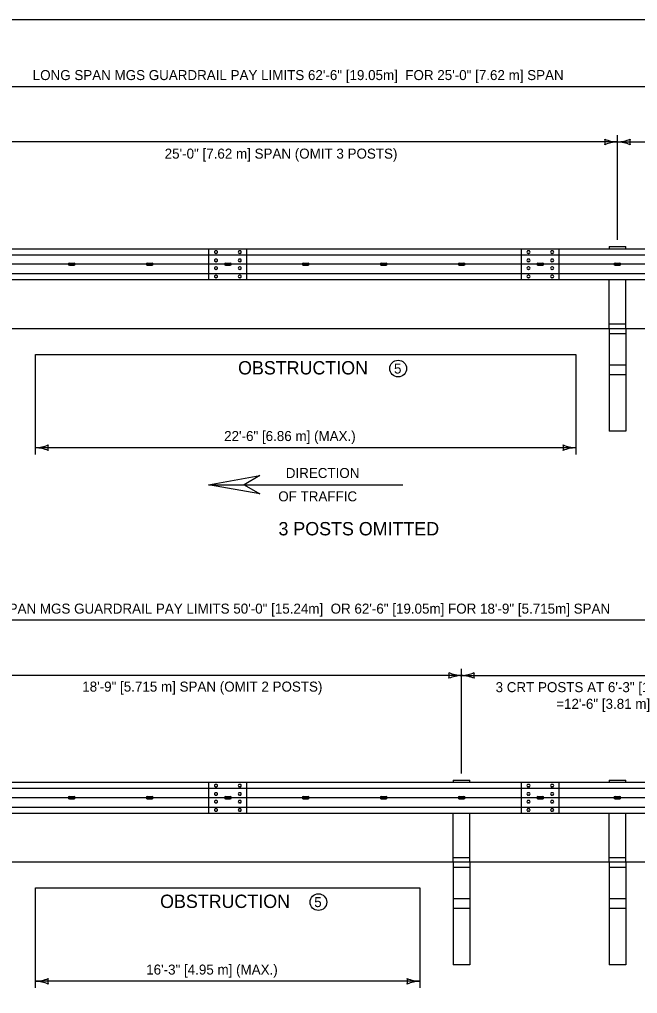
# Model space of a CAD drawing. Extents: x 49991.4 to 50021, y 49987.6 to 50011.4.
# Drawn here: x 50003.46 to 50007.16, y 49993.16 to 49999 of the extents above; entities that cross this region are included whole.
import ezdxf

# ---------------------------------------------------------------- set-up
doc = ezdxf.new("R2010")
doc.units = 0
for name, color, linetype in [('Level 1', 7, 'Continuous'), ('Level 2', 7, 'Continuous'), ('Level 3', 7, 'Continuous'), ('Level 4', 7, 'Continuous'), ('Level 5', 7, 'Continuous')]:
    doc.layers.add(name, color=color, linetype=linetype)

msp = doc.modelspace()

# ---------------------------------------------------------------- linework, layer by layer
at = {"layer": 'Level 1'}
for p, q in [((50000.0289, 49997.6246), (50011.2949, 49997.6246)), ((50004.5961, 49997.4394), (50004.5961, 49997.6239)), ((50004.6403, 49997.6123), (50004.6367, 49997.6123)), ((50004.6403, 49997.5973), (50004.6367, 49997.5973)), ((50004.7825, 49997.6123), (50004.7789, 49997.6123)), ((50004.7825, 49997.5973), (50004.7789, 49997.5973)), ((50006.4686, 49997.4394), (50006.4686, 49997.6239)), ((50006.5128, 49997.6123), (50006.5092, 49997.6123)), ((50006.5128, 49997.5973), (50006.5092, 49997.5973)), ((50006.655, 49997.6123), (50006.6514, 49997.6123)), ((50006.655, 49997.5973), (50006.6514, 49997.5973)), ((50006.9944, 49997.6379), (50006.9944, 49997.6246)), ((50006.9944, 49997.6379), (50007.0944, 49997.6379)), ((50007.0944, 49997.6246), (50007.0944, 49997.6379)), ((50000.0289, 49997.5886), (50011.2949, 49997.5886)), ((50003.7593, 49997.5386), (50003.7884, 49997.5386)), ((50004.2265, 49997.5386), (50004.2557, 49997.5386)), ((50004.6403, 49997.5624), (50004.6367, 49997.5624)), ((50004.6403, 49997.5474), (50004.6367, 49997.5474)), ((50004.6947, 49997.5386), (50004.7239, 49997.5386)), ((50004.7825, 49997.5624), (50004.7789, 49997.5624)), ((50004.7825, 49997.5474), (50004.7789, 49997.5474)), ((50005.1609, 49997.5386), (50005.1901, 49997.5386)), ((50005.6281, 49997.5386), (50005.6573, 49997.5386)), ((50006.0954, 49997.5386), (50006.1245, 49997.5386)), ((50006.5128, 49997.5624), (50006.5092, 49997.5624)), ((50006.5128, 49997.5474), (50006.5092, 49997.5474)), ((50006.5672, 49997.5386), (50006.5964, 49997.5386)), ((50006.655, 49997.5624), (50006.6514, 49997.5624)), ((50006.655, 49997.5474), (50006.6514, 49997.5474)), ((50007.0298, 49997.5386), (50007.059, 49997.5386)), ((50003.7593, 49997.5261), (50003.7884, 49997.5261)), ((50004.2265, 49997.5261), (50004.2557, 49997.5261)), ((50004.6403, 49997.516), (50004.6367, 49997.516)), ((50004.6403, 49997.5009), (50004.6367, 49997.5009)), ((50004.6947, 49997.5261), (50004.7239, 49997.5261)), ((50004.7825, 49997.516), (50004.7789, 49997.516)), ((50004.7825, 49997.5009), (50004.7789, 49997.5009)), ((50005.1609, 49997.5261), (50005.1901, 49997.5261)), ((50005.6281, 49997.5261), (50005.6573, 49997.5261)), ((50006.0954, 49997.5261), (50006.1245, 49997.5261)), ((50006.5128, 49997.516), (50006.5092, 49997.516)), ((50006.5128, 49997.5009), (50006.5092, 49997.5009)), ((50006.5672, 49997.5261), (50006.5964, 49997.5261)), ((50006.655, 49997.516), (50006.6514, 49997.516)), ((50006.655, 49997.5009), (50006.6514, 49997.5009)), ((50007.0298, 49997.5261), (50007.059, 49997.5261)), ((50000.0289, 49997.4761), (50011.2949, 49997.4761)), ((50000.0289, 49997.4401), (50011.2949, 49997.4401)), ((50004.6403, 49997.4661), (50004.6367, 49997.4661)), ((50004.6403, 49997.451), (50004.6367, 49997.451)), ((50004.7825, 49997.4661), (50004.7789, 49997.4661)), ((50004.7825, 49997.451), (50004.7789, 49997.451)), ((50006.5128, 49997.4661), (50006.5092, 49997.4661)), ((50006.5128, 49997.451), (50006.5092, 49997.451)), ((50006.655, 49997.4661), (50006.6514, 49997.4661)), ((50006.655, 49997.451), (50006.6514, 49997.451)), ((50006.9944, 49997.1457), (50006.9944, 49997.4401)), ((50007.0943, 49997.1457), (50007.0943, 49997.4401)), ((50011.2949, 49997.1457), (50000.0289, 49997.1457)), ((50003.5566, 49996.3921), (50003.5566, 49996.9912)), ((50003.5566, 49996.9912), (50006.7944, 49996.9912)), ((50006.7944, 49996.9912), (50006.7944, 49996.3921)), ((50004.5928, 49996.2105), (50005.7582, 49996.2105)), ((50000.0289, 49994.4263), (50010.4985, 49994.4263)), ((50000.0289, 49994.3903), (50010.4985, 49994.3903)), ((50004.5961, 49994.241), (50004.5961, 49994.4256)), ((50004.6403, 49994.414), (50004.6367, 49994.414)), ((50004.6403, 49994.3989), (50004.6367, 49994.3989)), ((50004.7825, 49994.414), (50004.7789, 49994.414)), ((50004.7825, 49994.3989), (50004.7789, 49994.3989)), ((50006.06, 49994.4396), (50006.06, 49994.4263)), ((50006.06, 49994.4396), (50006.1599, 49994.4396)), ((50006.1599, 49994.4263), (50006.1599, 49994.4396)), ((50006.4686, 49994.241), (50006.4686, 49994.4256)), ((50006.5128, 49994.414), (50006.5092, 49994.414)), ((50006.5128, 49994.3989), (50006.5092, 49994.3989)), ((50006.655, 49994.414), (50006.6514, 49994.414)), ((50006.655, 49994.3989), (50006.6514, 49994.3989)), ((50006.9944, 49994.4396), (50006.9944, 49994.4263)), ((50006.9944, 49994.4396), (50007.0944, 49994.4396)), ((50007.0944, 49994.4263), (50007.0944, 49994.4396)), ((50003.7593, 49994.3403), (50003.7884, 49994.3403)), ((50003.7593, 49994.3278), (50003.7884, 49994.3278)), ((50004.2265, 49994.3403), (50004.2557, 49994.3403)), ((50004.2265, 49994.3278), (50004.2557, 49994.3278)), ((50004.6403, 49994.3641), (50004.6367, 49994.3641)), ((50004.6403, 49994.349), (50004.6367, 49994.349)), ((50004.6947, 49994.3403), (50004.7239, 49994.3403)), ((50004.6947, 49994.3278), (50004.7239, 49994.3278)), ((50004.7825, 49994.3641), (50004.7789, 49994.3641)), ((50004.7825, 49994.349), (50004.7789, 49994.349)), ((50005.1609, 49994.3403), (50005.1901, 49994.3403)), ((50005.1609, 49994.3278), (50005.1901, 49994.3278)), ((50005.6281, 49994.3403), (50005.6573, 49994.3403)), ((50005.6281, 49994.3278), (50005.6573, 49994.3278)), ((50006.0954, 49994.3403), (50006.1245, 49994.3403)), ((50006.0954, 49994.3278), (50006.1245, 49994.3278)), ((50006.5128, 49994.3641), (50006.5092, 49994.3641)), ((50006.5128, 49994.349), (50006.5092, 49994.349)), ((50006.5672, 49994.3403), (50006.5964, 49994.3403)), ((50006.5672, 49994.3278), (50006.5964, 49994.3278)), ((50006.655, 49994.3641), (50006.6514, 49994.3641)), ((50006.655, 49994.349), (50006.6514, 49994.349)), ((50007.0298, 49994.3403), (50007.059, 49994.3403)), ((50007.0298, 49994.3278), (50007.059, 49994.3278)), ((50000.0289, 49994.2777), (50010.4985, 49994.2777)), ((50004.6403, 49994.3176), (50004.6367, 49994.3176)), ((50004.6403, 49994.3025), (50004.6367, 49994.3025)), ((50004.6403, 49994.2677), (50004.6367, 49994.2677)), ((50004.7825, 49994.3176), (50004.7789, 49994.3176)), ((50004.7825, 49994.3025), (50004.7789, 49994.3025)), ((50004.7825, 49994.2677), (50004.7789, 49994.2677)), ((50006.5128, 49994.3176), (50006.5092, 49994.3176)), ((50006.5128, 49994.3025), (50006.5092, 49994.3025)), ((50006.5128, 49994.2677), (50006.5092, 49994.2677)), ((50006.655, 49994.3176), (50006.6514, 49994.3176)), ((50006.655, 49994.3025), (50006.6514, 49994.3025)), ((50006.655, 49994.2677), (50006.6514, 49994.2677)), ((50000.0289, 49994.2417), (50010.4985, 49994.2417)), ((50004.6403, 49994.2526), (50004.6367, 49994.2526)), ((50004.7825, 49994.2526), (50004.7789, 49994.2526)), ((50006.06, 49993.9473), (50006.06, 49994.2417)), ((50006.1599, 49993.9473), (50006.1599, 49994.2417)), ((50006.5128, 49994.2526), (50006.5092, 49994.2526)), ((50006.655, 49994.2526), (50006.6514, 49994.2526)), ((50006.9944, 49993.9473), (50006.9944, 49994.2417)), ((50007.0943, 49993.9473), (50007.0943, 49994.2417)), ((50010.4985, 49993.9473), (50000.0289, 49993.9473)), ((50003.5566, 49993.1937), (50003.5566, 49993.7929)), ((50003.5566, 49993.7929), (50005.86, 49993.7929)), ((50005.86, 49993.7929), (50005.86, 49993.1937))]:
    msp.add_line(p, q, dxfattribs=at)
for points in [[(49999.3835, 49998.9992), (50016.7501, 49998.9992), (50016.7501, 49987.7988), (49999.3835, 49987.7988)], [(50004.9002, 49996.1563), (50004.5928, 49996.2105), (50004.9002, 49996.2651), (50004.8065, 49996.2105)]]:
    msp.add_lwpolyline(points, close=True, dxfattribs=at)
for centre, start, end in [((50003.7593, 49997.5324), 90, 180), ((50003.7884, 49997.5324), 360, 90), ((50004.2265, 49997.5324), 90, 180), ((50004.2557, 49997.5324), 360, 90), ((50004.6947, 49997.5324), 90, 180), ((50004.7239, 49997.5324), 360, 90), ((50005.1609, 49997.5324), 90, 180), ((50005.1901, 49997.5324), 360, 90), ((50005.6281, 49997.5324), 90, 180), ((50005.6573, 49997.5324), 360, 90), ((50006.0954, 49997.5324), 90, 180), ((50006.1245, 49997.5324), 360, 90), ((50006.5672, 49997.5324), 90, 180), ((50006.5964, 49997.5324), 360, 90), ((50007.0298, 49997.5324), 90, 180), ((50007.059, 49997.5324), 360, 90), ((50003.7593, 49997.5324), 180, 270), ((50003.7884, 49997.5324), 270, 0), ((50004.2265, 49997.5324), 180, 270), ((50004.2557, 49997.5324), 270, 0), ((50004.6947, 49997.5324), 180, 270), ((50004.7239, 49997.5324), 270, 0), ((50005.1609, 49997.5324), 180, 270), ((50005.1901, 49997.5324), 270, 0), ((50005.6281, 49997.5324), 180, 270), ((50005.6573, 49997.5324), 270, 0), ((50006.0954, 49997.5324), 180, 270), ((50006.1245, 49997.5324), 270, 0), ((50006.5672, 49997.5324), 180, 270), ((50006.5964, 49997.5324), 270, 0), ((50007.0298, 49997.5324), 180, 270), ((50007.059, 49997.5324), 270, 0), ((50003.7593, 49994.334), 90, 180), ((50003.7593, 49994.334), 180, 270), ((50003.7884, 49994.334), 360, 90), ((50003.7884, 49994.334), 270, 0), ((50004.2265, 49994.334), 90, 180), ((50004.2265, 49994.334), 180, 270), ((50004.2557, 49994.334), 360, 90), ((50004.2557, 49994.334), 270, 0), ((50004.6947, 49994.334), 90, 180), ((50004.6947, 49994.334), 180, 270), ((50004.7239, 49994.334), 360, 90), ((50004.7239, 49994.334), 270, 0), ((50005.1609, 49994.334), 90, 180), ((50005.1609, 49994.334), 180, 270), ((50005.1901, 49994.334), 360, 90), ((50005.1901, 49994.334), 270, 0), ((50005.6281, 49994.334), 90, 180), ((50005.6281, 49994.334), 180, 270), ((50005.6573, 49994.334), 360, 90), ((50005.6573, 49994.334), 270, 0), ((50006.0954, 49994.334), 90, 180), ((50006.0954, 49994.334), 180, 270), ((50006.1245, 49994.334), 360, 90), ((50006.1245, 49994.334), 270, 0), ((50006.5672, 49994.334), 90, 180), ((50006.5672, 49994.334), 180, 270), ((50006.5964, 49994.334), 360, 90), ((50006.5964, 49994.334), 270, 0), ((50007.0298, 49994.334), 90, 180), ((50007.0298, 49994.334), 180, 270), ((50007.059, 49994.334), 360, 90), ((50007.059, 49994.334), 270, 0)]:
    msp.add_arc(centre, 0.00625, start, end, dxfattribs=at)
for centre, start_param, end_param in [((50004.6367, 49997.6048), 1.570796, 4.712389), ((50004.6403, 49997.6048), 4.712389, 7.853982), ((50004.7789, 49997.6048), 1.570796, 4.712389), ((50004.7825, 49997.6048), 4.712389, 7.853982), ((50006.5092, 49997.6048), 1.570796, 4.712389), ((50006.5128, 49997.6048), 4.712389, 7.853982), ((50006.6514, 49997.6048), 1.570796, 4.712389), ((50006.655, 49997.6048), 4.712389, 7.853982), ((50004.6367, 49997.5549), 1.570796, 4.712389), ((50004.6403, 49997.5549), 4.712389, 7.853982), ((50004.7789, 49997.5549), 1.570796, 4.712389), ((50004.7825, 49997.5549), 4.712389, 7.853982), ((50006.5092, 49997.5549), 1.570796, 4.712389), ((50006.5128, 49997.5549), 4.712389, 7.853982), ((50006.6514, 49997.5549), 1.570796, 4.712389), ((50006.655, 49997.5549), 4.712389, 7.853982), ((50004.6367, 49997.5084), 1.570796, 4.712389), ((50004.6403, 49997.5084), 4.712389, 7.853982), ((50004.7789, 49997.5084), 1.570796, 4.712389), ((50004.7825, 49997.5084), 4.712389, 7.853982), ((50006.5092, 49997.5084), 1.570796, 4.712389), ((50006.5128, 49997.5084), 4.712389, 7.853982), ((50006.6514, 49997.5084), 1.570796, 4.712389), ((50006.655, 49997.5084), 4.712389, 7.853982), ((50004.6367, 49997.4585), 1.570796, 4.712389), ((50004.6403, 49997.4585), 4.712389, 7.853982), ((50004.7789, 49997.4585), 1.570796, 4.712389), ((50004.7825, 49997.4585), 4.712389, 7.853982), ((50006.5092, 49997.4585), 1.570796, 4.712389), ((50006.5128, 49997.4585), 4.712389, 7.853982), ((50006.6514, 49997.4585), 1.570796, 4.712389), ((50006.655, 49997.4585), 4.712389, 7.853982), ((50004.6367, 49994.4065), 1.570796, 4.712389), ((50004.6403, 49994.4065), 4.712389, 7.853982), ((50004.7789, 49994.4065), 1.570796, 4.712389), ((50004.7825, 49994.4065), 4.712389, 7.853982), ((50006.5092, 49994.4065), 1.570796, 4.712389), ((50006.5128, 49994.4065), 4.712389, 7.853982), ((50006.6514, 49994.4065), 1.570796, 4.712389), ((50006.655, 49994.4065), 4.712389, 7.853982), ((50004.6367, 49994.3566), 1.570796, 4.712389), ((50004.6403, 49994.3566), 4.712389, 7.853982), ((50004.7789, 49994.3566), 1.570796, 4.712389), ((50004.7825, 49994.3566), 4.712389, 7.853982), ((50006.5092, 49994.3566), 1.570796, 4.712389), ((50006.5128, 49994.3566), 4.712389, 7.853982), ((50006.6514, 49994.3566), 1.570796, 4.712389), ((50006.655, 49994.3566), 4.712389, 7.853982), ((50004.6367, 49994.3101), 1.570796, 4.712389), ((50004.6367, 49994.2602), 1.570796, 4.712389), ((50004.6403, 49994.3101), 4.712389, 7.853982), ((50004.6403, 49994.2602), 4.712389, 7.853982), ((50004.7789, 49994.3101), 1.570796, 4.712389), ((50004.7789, 49994.2602), 1.570796, 4.712389), ((50004.7825, 49994.3101), 4.712389, 7.853982), ((50004.7825, 49994.2602), 4.712389, 7.853982), ((50006.5092, 49994.3101), 1.570796, 4.712389), ((50006.5092, 49994.2602), 1.570796, 4.712389), ((50006.5128, 49994.3101), 4.712389, 7.853982), ((50006.5128, 49994.2602), 4.712389, 7.853982), ((50006.6514, 49994.3101), 1.570796, 4.712389), ((50006.6514, 49994.2602), 1.570796, 4.712389), ((50006.655, 49994.3101), 4.712389, 7.853982), ((50006.655, 49994.2602), 4.712389, 7.853982)]:
    msp.add_ellipse(centre, major_axis=(0.00756, 0), ratio=0.998676, start_param=start_param, end_param=end_param, dxfattribs=at)
at = {"layer": 'Level 2'}
for centre in [(50005.7301, 49996.9065), (50005.2521, 49993.7081)]:
    msp.add_circle(centre, 0.05, dxfattribs=at)
at = {"layer": 'Level 3'}
for p, q in [((50011.2949, 49998.5959), (50000.0289, 49998.5959)), ((50007.0444, 49997.6779), (50007.0444, 49998.3051)), ((50007.0444, 49998.2651), (50003.3066, 49998.2651)), ((50007.0444, 49998.2651), (50008.9133, 49998.2651)), ((50006.7944, 49996.4321), (50003.5566, 49996.4321)), ((50008.4543, 49995.3975), (50000.0289, 49995.3975)), ((50006.11, 49994.4796), (50006.11, 49995.1067)), ((50006.11, 49995.0667), (50003.3066, 49995.0667)), ((50006.11, 49995.0667), (50007.9788, 49995.0667)), ((50005.86, 49993.2337), (50003.5566, 49993.2337))]:
    msp.add_line(p, q, dxfattribs=at)
for centre, radius, start, end in [((50007.0535, 49998.4872), 0.2223, 247.45601, 267.63952), ((50006.9162, 49998.2651), 0.0548, 342.13882, 17.86118), ((50007.0559, 49998.0324), 0.233, 92.82731, 112.07716), ((50007.0329, 49998.4978), 0.233, 272.82731, 292.07716), ((50007.0352, 49998.043), 0.2223, 67.45601, 87.63952), ((50007.1726, 49998.2651), 0.0548, 162.13882, 197.86118), ((50003.5451, 49996.6648), 0.233, 272.82731, 292.07716), ((50003.5474, 49996.2099), 0.2223, 67.45601, 87.63952), ((50003.6848, 49996.4321), 0.0548, 162.13882, 197.86118), ((50006.8036, 49996.6542), 0.2223, 247.45601, 267.63952), ((50006.6662, 49996.4321), 0.0548, 342.13882, 17.86118), ((50006.8059, 49996.1994), 0.233, 92.82731, 112.07716), ((50006.1191, 49995.2889), 0.2223, 247.45601, 267.63952), ((50005.9817, 49995.0667), 0.0548, 342.13882, 17.86118), ((50006.1214, 49994.834), 0.233, 92.82731, 112.07716), ((50006.0985, 49995.2995), 0.233, 272.82731, 292.07716), ((50006.1008, 49994.8446), 0.2223, 67.45601, 87.63952), ((50006.2382, 49995.0667), 0.0548, 162.13882, 197.86118), ((50003.5451, 49993.4664), 0.233, 272.82731, 292.07716), ((50003.5474, 49993.0116), 0.2223, 67.45601, 87.63952), ((50003.6848, 49993.2337), 0.0548, 162.13882, 197.86118), ((50005.8691, 49993.4559), 0.2223, 247.45601, 267.63952), ((50005.7318, 49993.2337), 0.0548, 342.13882, 17.86118), ((50005.8715, 49993.001), 0.233, 92.82731, 112.07716)]:
    msp.add_arc(centre, radius, start, end, dxfattribs=at)
at = {"layer": 'Level 4'}
for p, q in [((50004.8226, 49997.4394), (50004.8226, 49997.6239)), ((50006.695, 49997.4394), (50006.695, 49997.6239)), ((50006.9944, 49997.1748), (50007.0943, 49997.1748)), ((50006.9944, 49997.1457), (50006.9944, 49996.5303)), ((50007.0943, 49997.1457), (50007.0943, 49996.5303)), ((50006.9944, 49997.1165), (50007.0943, 49997.1165)), ((50006.9944, 49996.9287), (50007.0943, 49996.9287)), ((50006.9944, 49996.8704), (50007.0943, 49996.8704)), ((50007.0943, 49996.5303), (50006.9944, 49996.5303)), ((50004.8226, 49994.241), (50004.8226, 49994.4256)), ((50006.695, 49994.241), (50006.695, 49994.4256)), ((50006.06, 49993.9765), (50006.1599, 49993.9765)), ((50006.9944, 49993.9765), (50007.0943, 49993.9765)), ((50006.06, 49993.9473), (50006.06, 49993.332)), ((50006.06, 49993.9182), (50006.1599, 49993.9182)), ((50006.1599, 49993.9473), (50006.1599, 49993.332)), ((50006.9944, 49993.9473), (50006.9944, 49993.332)), ((50006.9944, 49993.9182), (50007.0943, 49993.9182)), ((50007.0943, 49993.9473), (50007.0943, 49993.332)), ((50006.06, 49993.7304), (50006.1599, 49993.7304)), ((50006.9944, 49993.7304), (50007.0943, 49993.7304)), ((50006.06, 49993.6721), (50006.1599, 49993.6721)), ((50006.9944, 49993.6721), (50007.0943, 49993.6721)), ((50006.1599, 49993.332), (50006.06, 49993.332)), ((50007.0943, 49993.332), (50006.9944, 49993.332))]:
    msp.add_line(p, q, dxfattribs=at)
at = {"layer": 'Level 5'}
for p, q in [((50011.2949, 49997.5324), (50000.0289, 49997.5324)), ((50010.4985, 49994.334), (50000.0289, 49994.334))]:
    msp.add_line(p, q, dxfattribs=at)

# ---------------------------------------------------------------- texts
at = {"layer": 'Level 2'}
for s, height, p in [('LONG SPAN MGS GUARDRAIL PAY LIMITS 62\'-6" [19.05m]  FOR 25\'-0" [7.62 m] SPAN', 0.06, (50003.5399, 49998.6359)), ('25\'-0" [7.62 m] SPAN (OMIT 3 POSTS)', 0.06, (50004.3308, 49998.1651)), ('OBSTRUCTION', 0.08, (50004.7706, 49996.8712)), ('5', 0.06, (50005.7051, 49996.8766)), ('22\'-6" [6.86 m] (MAX.)', 0.06, (50004.6871, 49996.4721)), ('DIRECTION', 0.06, (50005.0566, 49996.2505)), ('OF TRAFFIC', 0.06, (50005.0115, 49996.1105)), ('3 POSTS OMITTED', 0.08, (50005.0127, 49995.9066)), ('LONG SPAN MGS GUARDRAIL PAY LIMITS 50\'-0" [15.24m]  OR 62\'-6" [19.05m] FOR 18\'-9" [5.715m] SPAN', 0.06, (50003.0923, 49995.4375)), ('18\'-9" [5.715 m] SPAN (OMIT 2 POSTS)', 0.06, (50003.8366, 49994.97)), ('3 CRT POSTS AT 6\'-3" [1.905 m]', 0.06, (50006.3141, 49994.9667)), (' =12\'-6" [3.81 m] ', 0.06, (50006.655, 49994.8667)), ('OBSTRUCTION', 0.08, (50004.3034, 49993.6729)), ('5', 0.06, (50005.2272, 49993.6781)), ('16\'-3" [4.95 m] (MAX.)', 0.06, (50004.2199, 49993.2737))]:
    msp.add_text(s, height=height, dxfattribs=at).set_placement(p)

doc.saveas('drawing.dxf')
